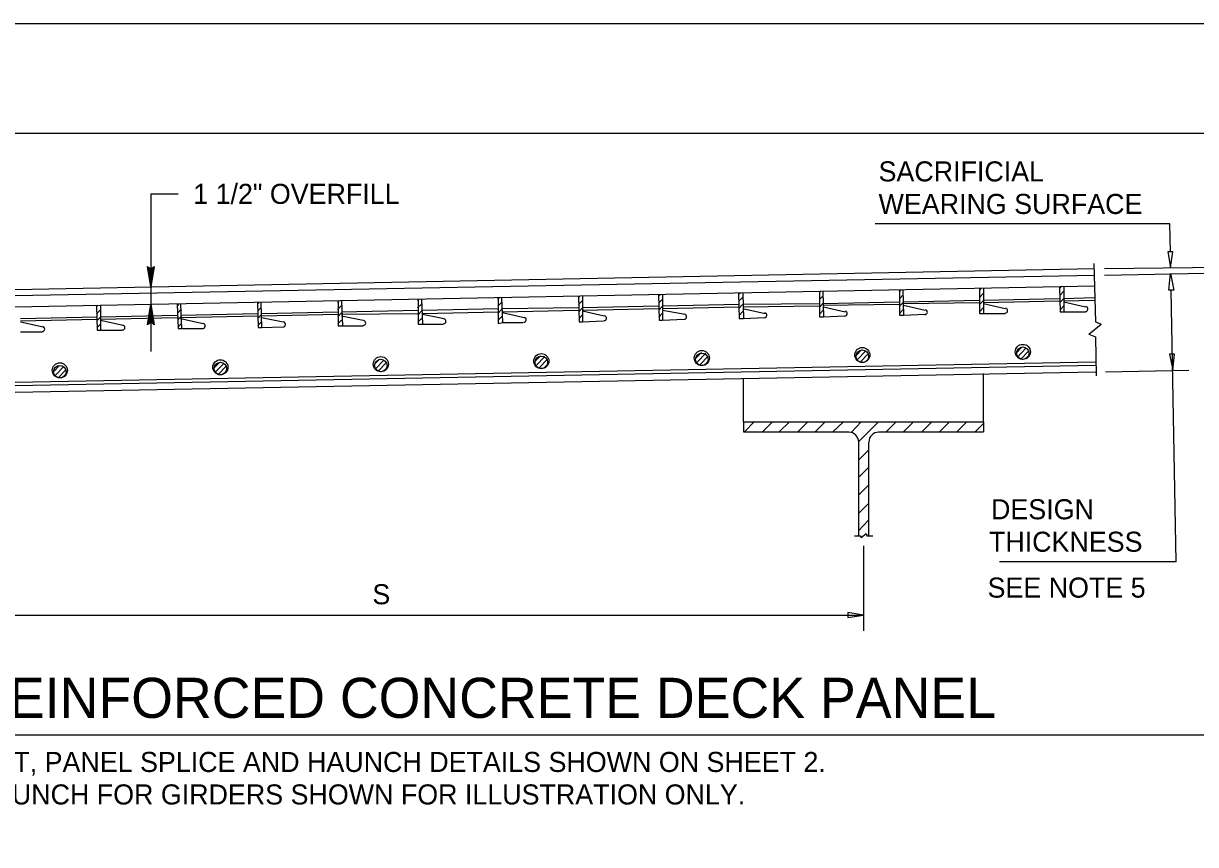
# Model space of a CAD drawing. Extents: x -24512 to -22484, y 4569 to 6351.
# Drawn here: x -24064.8 to -23889.5, y 6228.2 to 6351 of the extents above; entities that cross this region are included whole.
import ezdxf

# ---------------------------------------------------------------- set-up
doc = ezdxf.new("R2010")
doc.units = 0
for name, color, linetype in [('10', 7, 'Continuous'), ('11', 7, 'Continuous'), ('2', 7, 'Continuous'), ('4', 7, 'Continuous'), ('5', 7, 'Continuous'), ('6', 7, 'Continuous'), ('PLT-BNDY', 7, 'Continuous')]:
    doc.layers.add(name, color=color, linetype=linetype)

# ---------------------------------------------------------------- blocks, each defined once
blk = doc.blocks.new('JUQ005')
at = {"layer": '4'}
for p, q in [((12.764875, 6.492125), (12.825, 6.552375)), ((12.764875, 6.207), (12.916, 6.35825)), ((12.764875, 5.921875), (12.916, 6.073125)), ((12.764875, 5.63675), (12.916, 5.788))]:
    blk.add_line(p, q, dxfattribs=at)
blk = doc.blocks.new('JUQ006')
at = {"layer": '4'}
for p, q in [((10.418625, 11.48775), (10.630375, 11.699625)), ((10.457, 11.312375), (10.805875, 11.66125)), ((10.574625, 11.21625), (10.902, 11.5435)), ((10.82875, 11.256375), (10.86175, 11.2895))]:
    blk.add_line(p, q, dxfattribs=at)

msp = doc.modelspace()

# ---------------------------------------------------------------- linework, layer by layer
at = {"layer": '10'}
for p, q in [((-24041.64, 6325.52), (-24045.75, 6325.52)), ((-24045.75, 6325.52), (-24045.75, 6311.65)), ((-23893.36, 6321.05), (-23937.43, 6321.05)), ((-23893.29, 6316.9), (-23893.36, 6321.05)), ((-23903.14, 6314.4), (-23883, 6314.61)), ((-23903.14, 6313.41), (-23883.01, 6313.81)), ((-24045.75, 6311.65), (-24045.75, 6301.98)), ((-23892.42, 6270.51), (-23893.16, 6311.16)), ((-23903.01, 6298.94), (-23890.55, 6299.19)), ((-23939.17, 6272.88), (-23939.17, 6260.17)), ((-23892.42, 6270.51), (-23918.85, 6270.51)), ((-24083.19, 6262.53), (-23939.17, 6262.53))]:
    msp.add_line(p, q, dxfattribs=at)
for points in [[(-23892.92, 6316.9), (-23893.66, 6316.9), (-23893.29, 6314.53)], [(-23892.79, 6311.16), (-23893.54, 6311.16), (-23893.29, 6313.66)], [(-23892.67, 6301.56), (-23893.41, 6301.56), (-23892.92, 6299.19)], [(-23941.54, 6262.91), (-23941.54, 6262.16), (-23939.17, 6262.53)]]:
    msp.add_lwpolyline(points, close=True, dxfattribs=at)
for points in [[(-24045.38, 6314.55), (-24045.59, 6314.44), (-24045.75, 6311.65), (-24045.38, 6314.55), (-24045.26, 6314.7), (-24045.75, 6311.65), (-24045.89, 6314.44), (-24046.09, 6314.54), (-24045.75, 6311.65), (-24046.23, 6314.7), (-24046.09, 6314.54)], [(-24046.11, 6306.13), (-24045.9, 6306.24), (-24045.75, 6309.03), (-24046.11, 6306.13), (-24046.24, 6305.98), (-24045.75, 6309.03), (-24045.61, 6306.24), (-24045.4, 6306.14), (-24045.75, 6309.03), (-24045.26, 6305.98), (-24045.4, 6306.14)]]:
    msp.add_lwpolyline(points, dxfattribs=at)
at = {"layer": '11'}
msp.add_line((-23876.11, 6244.57), (-24132.21, 6244.57), dxfattribs=at)
at = {"layer": '2'}
msp.add_line((-24137.79, 6334.63), (-23353.75, 6334.63), dxfattribs=at)
at = {"layer": '5'}
for p, q in [((-23904.76, 6315.15), (-23904.51, 6306.42)), ((-24115.23, 6310.29), (-23904.64, 6314.4)), ((-24115.23, 6309.42), (-23904.64, 6313.41)), ((-24115.23, 6307.67), (-23904.64, 6311.79)), ((-23909.87, 6311.54), (-23909.75, 6307.92)), ((-23909.25, 6311.66), (-23909.25, 6307.92)), ((-24005.76, 6309.79), (-24005.76, 6306.05)), ((-24005.26, 6309.79), (-24005.13, 6306.05)), ((-23993.79, 6310.04), (-23993.79, 6306.18)), ((-23993.29, 6310.04), (-23993.16, 6306.3)), ((-23981.82, 6310.29), (-23981.69, 6306.42)), ((-23981.19, 6310.29), (-23981.19, 6306.42)), ((-23969.85, 6310.54), (-23969.72, 6306.67)), ((-23969.22, 6310.54), (-23969.22, 6306.67)), ((-23957.88, 6310.66), (-23957.75, 6306.92)), ((-23957.25, 6310.66), (-23957.13, 6306.92)), ((-23945.78, 6310.91), (-23945.78, 6307.17)), ((-23945.28, 6310.91), (-23945.16, 6307.17)), ((-23933.81, 6311.16), (-23933.81, 6307.42)), ((-23933.31, 6311.16), (-23933.19, 6307.42)), ((-23921.84, 6311.41), (-23921.84, 6307.67)), ((-23921.22, 6311.41), (-23921.22, 6307.67)), ((-23921.22, 6309.67), (-23909.87, 6309.92)), ((-23909.25, 6309.92), (-23904.64, 6310.04)), ((-24053.89, 6308.79), (-24053.76, 6305.18)), ((-24053.26, 6308.79), (-24053.26, 6305.18)), ((-24041.79, 6309.04), (-24041.67, 6305.43)), ((-24041.29, 6309.04), (-24041.17, 6305.43)), ((-24029.82, 6309.29), (-24029.7, 6305.55)), ((-24029.32, 6309.29), (-24029.2, 6305.55)), ((-24017.73, 6309.54), (-24017.73, 6305.8)), ((-24017.23, 6309.54), (-24017.1, 6305.8)), ((-24017.23, 6307.92), (-24005.76, 6308.17)), ((-24005.13, 6308.17), (-23993.79, 6308.42)), ((-23993.16, 6308.42), (-23981.82, 6308.54)), ((-23993.16, 6307.92), (-23981.82, 6308.17)), ((-23981.19, 6308.54), (-23969.85, 6308.79)), ((-23981.19, 6308.17), (-23969.72, 6308.42)), ((-23981.19, 6308.05), (-23977.95, 6307.3)), ((-23969.22, 6308.79), (-23957.75, 6309.04)), ((-23969.22, 6308.42), (-23957.75, 6308.67)), ((-23969.22, 6308.17), (-23965.86, 6307.55)), ((-23957.25, 6309.04), (-23945.78, 6309.17)), ((-23957.25, 6308.67), (-23945.78, 6308.79)), ((-23957.25, 6308.42), (-23953.89, 6307.67)), ((-23945.28, 6309.17), (-23933.81, 6309.42)), ((-23945.28, 6308.92), (-23933.81, 6309.04)), ((-23945.16, 6308.67), (-23941.92, 6307.92)), ((-23933.19, 6309.42), (-23921.84, 6309.67)), ((-23933.19, 6309.17), (-23921.84, 6309.29)), ((-23933.19, 6308.92), (-23929.95, 6308.17)), ((-23921.22, 6309.29), (-23909.87, 6309.54)), ((-23921.22, 6309.17), (-23917.98, 6308.42)), ((-23909.25, 6309.54), (-23904.64, 6309.67)), ((-23909.25, 6309.42), (-23906.01, 6308.67)), ((-24065.23, 6306.92), (-24053.76, 6307.17)), ((-24065.23, 6306.55), (-24053.76, 6306.8)), ((-24065.23, 6306.42), (-24061.87, 6305.68)), ((-24053.26, 6307.17), (-24041.79, 6307.42)), ((-24053.26, 6306.8), (-24041.79, 6307.05)), ((-24053.26, 6306.67), (-24049.9, 6305.93)), ((-24041.29, 6307.42), (-24029.7, 6307.67)), ((-24041.29, 6307.05), (-24029.7, 6307.3)), ((-24041.29, 6306.92), (-24037.93, 6306.18)), ((-24029.2, 6307.67), (-24017.73, 6307.92)), ((-24029.2, 6307.3), (-24017.73, 6307.55)), ((-24029.2, 6307.05), (-24025.96, 6306.42)), ((-24017.23, 6307.55), (-24005.76, 6307.67)), ((-24017.23, 6307.3), (-24013.99, 6306.67)), ((-24005.13, 6307.67), (-23993.79, 6307.92)), ((-24005.13, 6307.55), (-24001.89, 6306.92)), ((-23993.79, 6306.18), (-23993.16, 6306.3)), ((-23993.16, 6307.8), (-23989.92, 6307.05)), ((-23993.16, 6306.3), (-23990.05, 6306.3)), ((-23981.69, 6306.42), (-23981.19, 6306.42)), ((-23981.19, 6306.42), (-23978.08, 6306.55)), ((-23969.72, 6306.67), (-23969.22, 6306.67)), ((-23969.22, 6306.67), (-23965.98, 6306.8)), ((-23957.75, 6306.92), (-23957.13, 6306.92)), ((-23957.13, 6306.92), (-23954.01, 6307.05)), ((-23945.78, 6307.17), (-23945.16, 6307.17)), ((-23945.16, 6307.17), (-23942.04, 6307.3)), ((-23933.81, 6307.42), (-23933.19, 6307.42)), ((-23933.19, 6307.42), (-23929.95, 6307.55)), ((-23921.84, 6307.67), (-23921.22, 6307.67)), ((-23921.22, 6307.67), (-23917.98, 6307.67)), ((-23909.75, 6307.92), (-23909.25, 6307.92)), ((-23909.25, 6307.92), (-23906.01, 6307.92)), ((-23904.51, 6306.42), (-23903.64, 6306.05)), ((-24065.23, 6304.93), (-24061.99, 6304.93)), ((-24053.76, 6305.18), (-24053.26, 6305.18)), ((-24053.26, 6305.18), (-24050.02, 6305.18)), ((-24041.67, 6305.43), (-24041.17, 6305.43)), ((-24041.17, 6305.43), (-24037.93, 6305.43)), ((-24029.7, 6305.55), (-24029.2, 6305.55)), ((-24029.2, 6305.55), (-24025.96, 6305.68)), ((-24017.73, 6305.8), (-24017.1, 6305.8)), ((-24017.1, 6305.8), (-24013.99, 6305.8)), ((-24005.76, 6306.05), (-24005.13, 6306.05)), ((-24005.13, 6306.05), (-24002.02, 6306.05)), ((-23905.51, 6304.55), (-23903.64, 6306.05)), ((-23905.51, 6304.55), (-23904.51, 6304.18)), ((-23904.51, 6304.18), (-23904.39, 6298.32)), ((-24115.11, 6296.45), (-23904.51, 6300.44)), ((-24115.11, 6295.95), (-23904.51, 6299.94)), ((-24114.98, 6294.95), (-23904.51, 6298.94)), ((-23957.13, 6291.46), (-23957.13, 6297.95)), ((-23921.22, 6291.46), (-23921.22, 6298.69)), ((-23957.13, 6291.46), (-23957.13, 6289.97)), ((-23957.13, 6291.46), (-23921.22, 6291.46)), ((-23921.22, 6291.46), (-23921.22, 6289.97)), ((-23957.13, 6289.97), (-23941.42, 6289.97)), ((-23936.93, 6289.97), (-23921.22, 6289.97)), ((-23939.92, 6288.35), (-23939.92, 6274.38)), ((-23938.43, 6288.35), (-23938.43, 6274.38)), ((-23939.55, 6274.13), (-23938.8, 6274.75)), ((-23938.8, 6274.75), (-23938.68, 6274.38)), ((-23940.55, 6274.38), (-23939.67, 6274.38)), ((-23939.67, 6274.38), (-23939.55, 6274.13)), ((-23938.68, 6274.38), (-23937.8, 6274.38))]:
    msp.add_line(p, q, dxfattribs=at)
for centre, radius in [((-23915.36, 6301.91), 1.13), ((-24011.36, 6300.07), 1.13), ((-23987.36, 6300.53), 1.13), ((-23987.35, 6300.34), 0.938), ((-23963.36, 6300.99), 1.13), ((-23963.36, 6300.8), 0.938), ((-23939.36, 6301.45), 1.13), ((-23939.36, 6301.26), 0.938), ((-23915.36, 6301.72), 0.938), ((-24059.35, 6299.15), 1.13), ((-24059.35, 6298.96), 0.938), ((-24035.35, 6299.61), 1.13), ((-24035.35, 6299.42), 0.938), ((-24011.35, 6299.88), 0.938)]:
    msp.add_circle(centre, radius, dxfattribs=at)
for centre, radius, start, end in [((-23942, 6307.63), 0.375, 271.0964, 77.9991), ((-23930, 6307.86), 0.375, 271.0964, 77.9991), ((-23918, 6308.09), 0.375, 271.0964, 77.9991), ((-23906, 6308.32), 0.375, 271.0964, 77.9991), ((-24025.99, 6306.02), 0.375, 271.0964, 77.9991), ((-24013.99, 6306.25), 0.375, 271.0964, 77.9991), ((-24001.99, 6306.48), 0.375, 271.0964, 77.9991), ((-23989.99, 6306.71), 0.375, 271.0964, 77.9991), ((-23977.99, 6306.94), 0.375, 271.0964, 77.9991), ((-23966, 6307.17), 0.375, 271.0964, 77.9991), ((-23954, 6307.4), 0.375, 271.0964, 77.9991), ((-24061.99, 6305.33), 0.375, 271.0964, 77.9991), ((-24049.99, 6305.56), 0.375, 271.0964, 77.9991), ((-24037.99, 6305.79), 0.375, 271.0964, 77.9991), ((-23941.4, 6288.4), 1.5, 0, 90), ((-23936.89, 6288.4), 1.5, 90, 180)]:
    msp.add_arc(centre, radius, start, end, dxfattribs=at)
at = {"layer": '6'}
for p, q in [((-23957, 6289.97), (-23955.51, 6291.46)), ((-23954.26, 6289.97), (-23952.77, 6291.46)), ((-23951.77, 6289.97), (-23950.27, 6291.46)), ((-23949.02, 6289.97), (-23947.53, 6291.46)), ((-23946.41, 6289.97), (-23944.91, 6291.46)), ((-23943.79, 6289.97), (-23942.17, 6291.46)), ((-23941.04, 6289.84), (-23939.55, 6291.46)), ((-23939.92, 6288.47), (-23936.93, 6291.46)), ((-23935.81, 6289.97), (-23934.31, 6291.46)), ((-23933.19, 6289.97), (-23931.69, 6291.46)), ((-23930.45, 6289.97), (-23928.95, 6291.46)), ((-23927.83, 6289.97), (-23926.33, 6291.46)), ((-23925.21, 6289.97), (-23923.71, 6291.46)), ((-23922.47, 6289.97), (-23921.22, 6291.21)), ((-23939.92, 6285.73), (-23938.43, 6287.22)), ((-23939.92, 6283.11), (-23938.43, 6284.6)), ((-23939.92, 6280.49), (-23938.43, 6281.99)), ((-23939.92, 6277.75), (-23938.43, 6279.24)), ((-23939.92, 6275.13), (-23938.43, 6276.75))]:
    msp.add_line(p, q, dxfattribs=at)
at = {"layer": 'PLT-BNDY'}
msp.add_lwpolyline([(-23338.75, 5757.04), (-24179.75, 5757.04), (-24179.75, 6351.04), (-23338.75, 6351.04)], close=True, dxfattribs=at)

# ---------------------------------------------------------------- block references
at = {"layer": '4', "xscale": 3.720483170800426, "yscale": 3.720483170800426, "rotation": 1.0964384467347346}
for name, p in [('JUQ005', (-23956.88, 6286.35)), ('JUQ005', (-24052.89, 6284.48)), ('JUQ005', (-24040.92, 6284.73)), ('JUQ005', (-24028.82, 6284.98)), ('JUQ005', (-24016.85, 6285.23)), ('JUQ005', (-24004.88, 6285.48)), ('JUQ005', (-23992.79, 6285.73)), ('JUQ005', (-23980.82, 6285.85)), ('JUQ005', (-23968.85, 6286.1)), ('JUQ005', (-24100.89, 6283.61)), ('JUQ005', (-24088.8, 6283.73)), ('JUQ005', (-24076.83, 6283.98)), ('JUQ005', (-24064.86, 6284.23)), ('JUQ006', (-24026.21, 6257.05)), ('JUQ006', (-24002.14, 6257.55)), ('JUQ006', (-23978.2, 6257.92)), ('JUQ006', (-23954.26, 6258.3)), ('JUQ006', (-24098.15, 6255.55)), ('JUQ006', (-24074.21, 6256.05)), ('JUQ006', (-24050.27, 6256.55))]:
    msp.add_blockref(name, p, dxfattribs=at)

# ---------------------------------------------------------------- texts
at = {"layer": '10'}
for s, p in [('SACRIFICIAL', (-23936.93, 6327.41)), ('1 1/2" OVERFILL', (-24039.41, 6324.05)), ('WEARING SURFACE', (-23936.93, 6322.54)), ('DESIGN', (-23920.11, 6276.87)), ('THICKNESS', (-23920.42, 6272.01)), ('SEE NOTE 5', (-23920.63, 6265.15)), ('S', (-24012.62, 6264.16)), ('DECK ATTACHMENT, PANEL SPLICE AND HAUNCH DETAILS SHOWN ON SHEET 2.', (-24103.53, 6239.07)), ('TYPICAL HAUNCH FOR GIRDERS SHOWN FOR ILLUSTRATION ONLY.', (-24089.94, 6234.21))]:
    msp.add_text(s, height=3, dxfattribs=at).set_placement(p)
at = {"layer": '11'}
msp.add_text('TYPICAL GRID REINFORCED CONCRETE DECK PANEL', height=6.0008, dxfattribs=at).set_placement((-24130.72, 6247.16))

doc.saveas('drawing.dxf')
